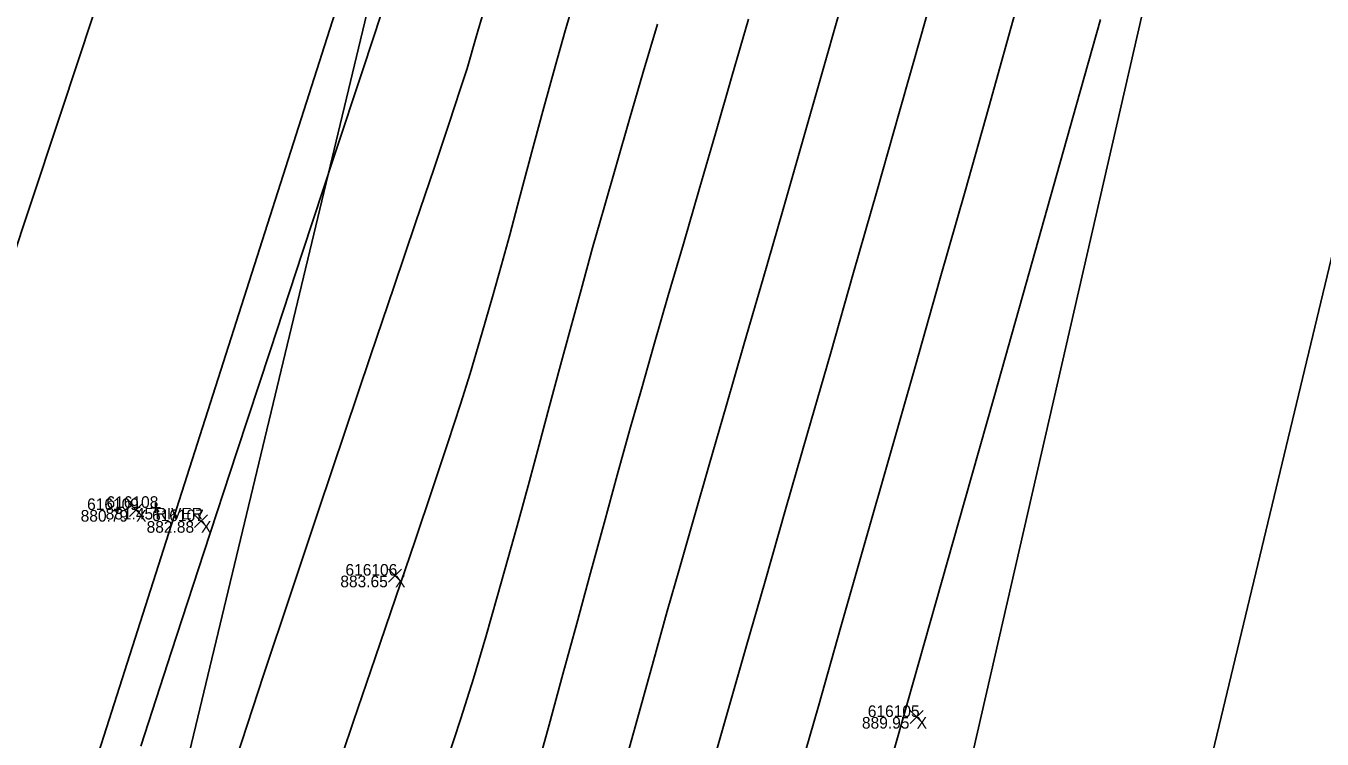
# Model space of a CAD drawing. Extents: x 1957117 to 1971063, y 701601 to 715861.
# Drawn here: x 1963046.46 to 1963085.54, y 705038.52 to 705060 of the extents above; entities that cross this region are included whole.
import ezdxf

# ---------------------------------------------------------------- set-up
doc = ezdxf.new("R2010")
doc.units = 0
for name, color, linetype in [('AP_X_Lights', 7, 'Continuous'), ('DT_X_Break_Line', 7, 'Continuous'), ('DT_X_Contour_Major', 7, 'Continuous'), ('DT_X_Contour_Minor', 7, 'Continuous'), ('GE_X_CL_20', 7, 'Continuous'), ('HY_X_Water_Edge', 7, 'Continuous'), ('PV_P_Drive', 7, 'Continuous'), ('PV_P_Shoulder', 7, 'Continuous'), ('RS_Raster1', 7, 'Continuous'), ('RW_X_Esmt_RR', 7, 'Continuous'), ('SC_Scratch1', 7, 'Continuous'), ('SC_Shading5', 7, 'Continuous')]:
    doc.layers.add(name, color=color, linetype=linetype)

msp = doc.modelspace()

# ---------------------------------------------------------------- linework, layer by layer
at = {"layer": 'AP_X_Lights'}
for p, q in [((1963049.588, 705045.223), (1963049.976, 705045.613)), ((1963049.588, 705045.613), (1963049.976, 705045.223)), ((1963051.544, 705044.888), (1963051.932, 705045.278)), ((1963051.544, 705045.278), (1963051.932, 705044.888)), ((1963057.398, 705043.246), (1963057.786, 705043.636)), ((1963057.398, 705043.636), (1963057.786, 705043.246)), ((1963073.125, 705038.987), (1963073.513, 705039.377)), ((1963073.125, 705039.377), (1963073.513, 705038.987))]:
    msp.add_line(p, q, dxfattribs=at)
at = {"layer": 'DT_X_Break_Line'}
for points in [[(1962854.549, 704243.654), (1962868.069, 704295.231), (1962879.669, 704344.313), (1962892.757, 704392.318), (1962905.964, 704443.142), (1962917.718, 704492.375), (1962926.962, 704538.336), (1962936.778, 704587.265), (1962949.215, 704630.669), (1962963.968, 704683.754), (1962972.038, 704733.348), (1962988.206, 704780.999), (1962994.689, 704830.943), (1963004.932, 704879.138), (1963021.822, 704927.498), (1963031.944, 704976.286), (1963045.21, 705027.355), (1963059.618, 705072.384), (1963067.267, 705121.949)], [(1963081.686, 705067.168), (1963070.617, 705018.992), (1963060.629, 704969.66), (1963044.793, 704921.859), (1963033.624, 704869.219), (1963022.038, 704824.561), (1963012.554, 704778.141), (1962998.858, 704727.004), (1962987.967, 704677.611), (1962975.675, 704626.305), (1962966.447, 704580.213), (1962950.262, 704533.092), (1962939.515, 704481.257), (1962926.044, 704436.037), (1962917.68, 704386.811), (1962906.11, 704337.415), (1962892.064, 704289.931), (1962881.011, 704234.451)]]:
    msp.add_lwpolyline(points, dxfattribs=at)
at = {"layer": 'DT_X_Contour_Major'}
for points in [[(1963078.863, 705060.2), (1963078.141, 705057.641), (1963077.353, 705054.852), (1963076.517, 705051.894), (1963075.65, 705048.829), (1963074.77, 705045.719), (1963073.895, 705042.627), (1963073.043, 705039.615), (1963072.23, 705036.743)], [(1963078.863, 705060.2), (1963078.141, 705057.641), (1963077.353, 705054.852), (1963076.517, 705051.894), (1963075.65, 705048.829), (1963074.77, 705045.719), (1963073.895, 705042.627), (1963073.043, 705039.615), (1963072.23, 705036.743)], [(1963065.502, 705060.063), (1963065.076, 705058.608), (1963064.662, 705057.194), (1963064.266, 705055.832), (1963063.892, 705054.534), (1963063.547, 705053.314), (1963063.198, 705052.056), (1963062.867, 705050.844), (1963062.549, 705049.668), (1963062.24, 705048.518), (1963061.936, 705047.384), (1963061.631, 705046.255), (1963061.322, 705045.123), (1963061.005, 705043.975), (1963060.673, 705042.804), (1963060.324, 705041.597), (1963059.953, 705040.346), (1963059.576, 705039.134), (1963059.156, 705037.849)], [(1963065.502, 705060.063), (1963065.076, 705058.608), (1963064.662, 705057.194), (1963064.266, 705055.832), (1963063.892, 705054.534), (1963063.547, 705053.314), (1963063.198, 705052.056), (1963062.867, 705050.844), (1963062.549, 705049.668), (1963062.24, 705048.518), (1963061.936, 705047.384), (1963061.631, 705046.255), (1963061.322, 705045.123), (1963061.005, 705043.975), (1963060.673, 705042.804), (1963060.324, 705041.597), (1963059.953, 705040.346), (1963059.576, 705039.134), (1963059.156, 705037.849)]]:
    msp.add_lwpolyline(points, dxfattribs=at)
at = {"layer": 'DT_X_Contour_Minor'}
for points in [[(1963045.558, 705051.503), (1963046.54, 705054.446), (1963047.523, 705057.403), (1963048.49, 705060.321), (1963049.423, 705063.146), (1963050.304, 705065.826), (1963051.115, 705068.307), (1963051.838, 705070.537), (1963052.455, 705072.463), (1963052.948, 705074.032), (1963053.403, 705075.524), (1963053.956, 705077.369), (1963054.593, 705079.521), (1963055.3, 705081.931), (1963056.064, 705084.552), (1963056.872, 705087.338), (1963057.711, 705090.239), (1963058.566, 705093.21), (1963059.426, 705096.203), (1963060.275, 705099.169), (1963061.102, 705102.063)], [(1963045.558, 705051.503), (1963046.54, 705054.446), (1963047.523, 705057.403), (1963048.49, 705060.321), (1963049.423, 705063.146), (1963050.304, 705065.826), (1963051.115, 705068.307), (1963051.838, 705070.537), (1963052.455, 705072.463), (1963052.948, 705074.032), (1963053.403, 705075.524), (1963053.956, 705077.369), (1963054.593, 705079.521), (1963055.3, 705081.931), (1963056.064, 705084.552), (1963056.872, 705087.338), (1963057.711, 705090.239), (1963058.566, 705093.21), (1963059.426, 705096.203), (1963060.275, 705099.169), (1963061.102, 705102.063)], [(1963076.775, 705062.123), (1963076.162, 705059.938), (1963075.491, 705057.557), (1963074.776, 705055.031), (1963074.031, 705052.407), (1963073.27, 705049.733), (1963072.508, 705047.059), (1963071.759, 705044.431), (1963071.036, 705041.9), (1963070.355, 705039.512), (1963069.728, 705037.318)], [(1963076.775, 705062.123), (1963076.162, 705059.938), (1963075.491, 705057.557), (1963074.776, 705055.031), (1963074.031, 705052.407), (1963073.27, 705049.733), (1963072.508, 705047.059), (1963071.759, 705044.431), (1963071.036, 705041.9), (1963070.355, 705039.512), (1963069.728, 705037.318)], [(1963074.076, 705061.95), (1963073.46, 705059.755), (1963072.802, 705057.43), (1963072.117, 705055.021), (1963071.417, 705052.573), (1963070.717, 705050.129), (1963070.029, 705047.734), (1963069.368, 705045.433), (1963068.746, 705043.271), (1963068.178, 705041.292), (1963067.676, 705039.542), (1963067.255, 705038.063)], [(1963074.076, 705061.95), (1963073.46, 705059.755), (1963072.802, 705057.43), (1963072.117, 705055.021), (1963071.417, 705052.573), (1963070.717, 705050.129), (1963070.029, 705047.734), (1963069.368, 705045.433), (1963068.746, 705043.271), (1963068.178, 705041.292), (1963067.676, 705039.542), (1963067.255, 705038.063)], [(1963057.447, 705061.197), (1963056.636, 705058.742), (1963055.748, 705056.054), (1963054.803, 705053.19), (1963053.822, 705050.211), (1963052.823, 705047.173), (1963051.827, 705044.136), (1963050.854, 705041.158), (1963049.923, 705038.298)], [(1963057.447, 705061.197), (1963056.636, 705058.742), (1963055.748, 705056.054), (1963054.803, 705053.19), (1963053.822, 705050.211), (1963052.823, 705047.173), (1963051.827, 705044.136), (1963050.854, 705041.158), (1963049.923, 705038.298)], [(1963063.032, 705060.921), (1963062.724, 705059.86), (1963062.42, 705058.784), (1963062.078, 705057.55), (1963061.784, 705056.469), (1963061.525, 705055.498), (1963061.285, 705054.593), (1963061.049, 705053.711), (1963060.803, 705052.807), (1963060.532, 705051.84), (1963060.221, 705050.764), (1963059.857, 705049.536), (1963059.568, 705048.612), (1963059.185, 705047.443), (1963058.723, 705046.061), (1963058.194, 705044.499), (1963057.611, 705042.788), (1963056.989, 705040.962), (1963056.339, 705039.052), (1963055.676, 705037.091)], [(1963063.032, 705060.921), (1963062.724, 705059.86), (1963062.42, 705058.784), (1963062.078, 705057.55), (1963061.784, 705056.469), (1963061.525, 705055.498), (1963061.285, 705054.593), (1963061.049, 705053.711), (1963060.803, 705052.807), (1963060.532, 705051.84), (1963060.221, 705050.764), (1963059.857, 705049.536), (1963059.568, 705048.612), (1963059.185, 705047.443), (1963058.723, 705046.061), (1963058.194, 705044.499), (1963057.611, 705042.788), (1963056.989, 705040.962), (1963056.339, 705039.052), (1963055.676, 705037.091)], [(1963071.014, 705060.498), (1963070.443, 705058.489), (1963069.859, 705056.45), (1963069.271, 705054.41), (1963068.688, 705052.394), (1963068.119, 705050.431), (1963067.573, 705048.549), (1963067.059, 705046.775), (1963066.586, 705045.135), (1963066.164, 705043.659), (1963065.8, 705042.373), (1963065.382, 705040.872), (1963064.899, 705039.139), (1963064.37, 705037.232)], [(1963071.014, 705060.498), (1963070.443, 705058.489), (1963069.859, 705056.45), (1963069.271, 705054.41), (1963068.688, 705052.394), (1963068.119, 705050.431), (1963067.573, 705048.549), (1963067.059, 705046.775), (1963066.586, 705045.135), (1963066.164, 705043.659), (1963065.8, 705042.373), (1963065.382, 705040.872), (1963064.899, 705039.139), (1963064.37, 705037.232)], [(1963060.265, 705060.46), (1963060.04, 705059.672), (1963059.761, 705058.727), (1963059.558, 705058.091), (1963059.221, 705057.073), (1963058.766, 705055.718), (1963058.208, 705054.067), (1963057.565, 705052.167), (1963056.852, 705050.06), (1963056.085, 705047.79), (1963055.281, 705045.4), (1963054.456, 705042.936), (1963053.626, 705040.44), (1963052.808, 705037.956)], [(1963060.265, 705060.46), (1963060.04, 705059.672), (1963059.761, 705058.727), (1963059.558, 705058.091), (1963059.221, 705057.073), (1963058.766, 705055.718), (1963058.208, 705054.067), (1963057.565, 705052.167), (1963056.852, 705050.06), (1963056.085, 705047.79), (1963055.281, 705045.4), (1963054.456, 705042.936), (1963053.626, 705040.44), (1963052.808, 705037.956)], [(1963068.246, 705060.208), (1963067.747, 705058.477), (1963067.249, 705056.759), (1963066.759, 705055.073), (1963066.283, 705053.44), (1963065.83, 705051.881), (1963065.406, 705050.415), (1963065.018, 705049.062), (1963064.673, 705047.843), (1963064.291, 705046.467), (1963063.893, 705045.021), (1963063.484, 705043.527), (1963063.069, 705042.003), (1963062.652, 705040.471), (1963062.238, 705038.949), (1963061.83, 705037.458)], [(1963068.246, 705060.208), (1963067.747, 705058.477), (1963067.249, 705056.759), (1963066.759, 705055.073), (1963066.283, 705053.44), (1963065.83, 705051.881), (1963065.406, 705050.415), (1963065.018, 705049.062), (1963064.673, 705047.843), (1963064.291, 705046.467), (1963063.893, 705045.021), (1963063.484, 705043.527), (1963063.069, 705042.003), (1963062.652, 705040.471), (1963062.238, 705038.949), (1963061.83, 705037.458)]]:
    msp.add_lwpolyline(points, dxfattribs=at)
at = {"layer": 'GE_X_CL_20'}
msp.add_lwpolyline([(1963418.3, 706437.397), (1962895.621, 704261.062)], dxfattribs=at)
at = {"layer": 'HY_X_Water_Edge'}
msp.add_spline([(1963191.723, 701994.048), (1963062.047, 702441.167), (1962863.491, 703169.356), (1962827.53, 703438.691), (1962823.213, 703537.412), (1962817.962, 703593.874), (1962817.97, 703697.316), (1962828.582, 703804.235), (1962836.461, 703844.734), (1962850.687, 703896.004), (1962867.251, 703938.846), (1962873.848, 703992.355), (1962884.135, 704091.371), (1962891.241, 704140.854), (1962897.382, 704180.529), (1962905.467, 704230.979), (1962943.949, 704328.022), (1962948.537, 704378.842), (1962964.114, 704426.264), (1963004.885, 704570.73), (1963042.054, 704716.522), (1963062.038, 704814.417), (1963072.171, 704860.237), (1963090.023, 704956.798), (1963107.066, 705031.783), (1963133.773, 705105.742), (1963148.685, 705206.74), (1963175.48, 705301.059), (1963191.635, 705353.417), (1963210.988, 705447.286), (1963219.532, 705497.27), (1963230.124, 705549.475), (1963251.052, 705591.159), (1963275.289, 705693.429), (1963292.982, 705784.032), (1963302.841, 705839.645), (1963335.126, 705936.766), (1963359.752, 706046.75), (1963389.133, 706177.299), (1963417.827, 706273.456), (1963475.868, 706451.902), (1963533.782, 706640.53), (1963553.86, 706696.984), (1963580.184, 706715.425), (1963609.172, 706718.73), (1963617.062, 706714.691), (1963619.447, 706694.678), (1963564.282, 706533.07), (1963531.853, 706395.229), (1963434.4, 706006.96), (1963354.09, 705679.186), (1963237.513, 705206.07), (1963167.369, 704892.962), (1963059.145, 704434.176), (1962907.914, 703908.742), (1962877.458, 703703.326), (1962898.357, 703412.121), (1962942.65, 703052.267), (1963048.963, 702674.866), (1963191.468, 702189.666), (1963245.396, 702019.832)], degree=3, dxfattribs=at)
at = {"layer": 'PV_P_Drive'}
for p, q in [((1963050.223, 705045.483), (1963050.515, 705045.483)), ((1963050.369, 705045.629), (1963050.369, 705045.337)), ((1963050.369, 705045.483), (1963050.369, 705045.483))]:
    msp.add_line(p, q, dxfattribs=at)
at = {"layer": 'RW_X_Esmt_RR'}
msp.add_lwpolyline([(1962866.45, 704268.068), (1963123.345, 705337.727), (1963135.496, 705336.937), (1963400.797, 706441.601)], dxfattribs=at)
at = {"layer": 'SC_Shading5'}
for points in [[(1963026.912, 704294.121), (1963138.818, 704737.794), (1963251.679, 705213.963), (1963374.306, 705730.111), (1963454.783, 706045.593), (1963517.244, 706296.713), (1963562.763, 706479.256), (1963580.13, 706553.799), (1963589.678, 706586.994)], [(1963609.915, 706579.703), (1963587.283, 706499.153), (1963552.056, 706354.005), (1963480.911, 706069.234), (1963357.401, 705576.869), (1963272.751, 705226.931), (1963210.247, 704956.481), (1963044.97, 704288.881)]]:
    msp.add_spline(points, degree=3, dxfattribs=at)

# ---------------------------------------------------------------- texts
at = {"layer": 'PV_P_Shoulder'}
for s, p in [('880.79', (1963048.112, 705045.068)), ('881.45', (1963048.865, 705045.133)), ('882.88', (1963050.101, 705044.733)), ('883.65', (1963055.941, 705043.091)), ('889.95', (1963071.668, 705038.832))]:
    msp.add_text(s, height=0.35, dxfattribs=at).set_placement(p)
at = {"layer": 'RS_Raster1'}
for s, p in [('616109', (1963048.305, 705045.418)), ('616108', (1963048.892, 705045.483)), ('616107', (1963050.264, 705045.083)), ('616106', (1963056.096, 705043.441)), ('616105', (1963071.845, 705039.182))]:
    msp.add_text(s, height=0.35, dxfattribs=at).set_placement(p)
at = {"layer": 'SC_Scratch1'}
for s, p in [('X', (1963049.782, 705045.068)), ('RIVER', (1963050.369, 705045.133)), ('X', (1963051.738, 705044.733)), ('X', (1963057.592, 705043.091)), ('X', (1963073.319, 705038.832))]:
    msp.add_text(s, height=0.35, dxfattribs=at).set_placement(p)

doc.saveas('drawing.dxf')
